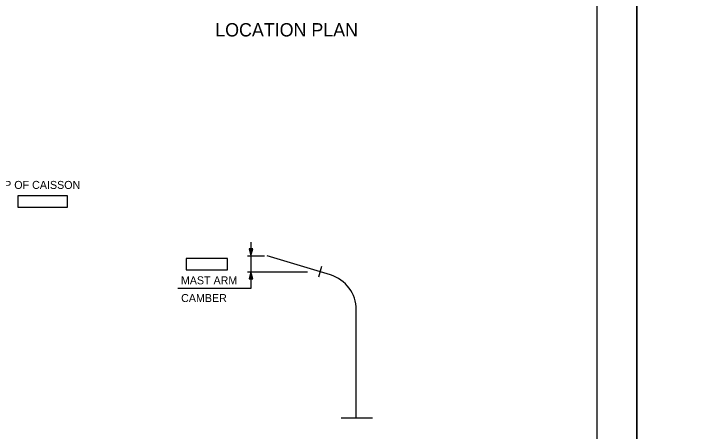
# Model space of a CAD drawing. Extents: x 640117 to 642655, y 297247 to 298435.
# Drawn here: x 640724.9 to 640985.6, y 297508.5 to 297665 of the extents above; entities that cross this region are included whole.
import ezdxf

# ---------------------------------------------------------------- set-up
doc = ezdxf.new("R2010")
doc.units = 0
for name, color, linetype in [('10', 7, 'Continuous'), ('2', 7, 'Continuous'), ('20', 7, 'Continuous'), ('50', 7, 'Continuous'), ('53', 7, 'Continuous'), ('PLT-BNDY', 7, 'Continuous')]:
    doc.layers.add(name, color=color, linetype=linetype)

msp = doc.modelspace()

# ---------------------------------------------------------------- linework, layer by layer
at = {"layer": '10'}
for p, q in [((640813.14, 297576.86), (640813.8, 297574.21)), ((640814.46, 297576.86), (640813.14, 297576.86)), ((640813.34, 297576.7), (640813.8, 297574.86)), ((640814.26, 297576.7), (640813.34, 297576.7)), ((640813.54, 297576.55), (640813.8, 297575.51)), ((640814.06, 297576.55), (640813.54, 297576.55)), ((640813.72, 297576.48), (640813.8, 297576.15)), ((640813.8, 297574.21), (640814.46, 297576.86)), ((640813.8, 297574.86), (640814.26, 297576.7)), ((640813.8, 297575.51), (640814.06, 297576.55)), ((640813.8, 297576.15), (640813.88, 297576.47)), ((640812.47, 297574.21), (640818.85, 297574.21)), ((640812.47, 297568.23), (640834.98, 297568.23)), ((640813.8, 297568.23), (640813.14, 297565.58)), ((640813.8, 297567.58), (640813.34, 297565.74)), ((640814.46, 297565.58), (640813.8, 297568.23)), ((640814.26, 297565.74), (640813.8, 297567.58)), ((640813.14, 297565.58), (640814.46, 297565.58)), ((640813.34, 297565.74), (640814.26, 297565.74)), ((640813.8, 297566.93), (640813.54, 297565.89)), ((640813.54, 297565.89), (640814.06, 297565.89)), ((640813.8, 297566.29), (640813.72, 297565.97)), ((640814.06, 297565.89), (640813.8, 297566.93)), ((640813.88, 297565.96), (640813.8, 297566.29)), ((640813.8, 297561.93), (640786.43, 297561.93))]:
    msp.add_line(p, q, dxfattribs=at)
msp.add_lwpolyline([(640813.8, 297579.34), (640813.8, 297561.93)], dxfattribs=at)
at = {"layer": '2'}
msp.add_line((640943.46, 297826.46), (640943.46, 297262.46), dxfattribs=at)
for points in [[(640726.36, 297592.43), (640745.07, 297592.43), (640745.07, 297596.68), (640726.36, 297596.68)], [(640789.56, 297568.94), (640805, 297568.94), (640805, 297573.19), (640789.56, 297573.19)]]:
    msp.add_lwpolyline(points, close=True, dxfattribs=at)
at = {"layer": '20'}
for p, q in [((640843.62, 297567.05), (640819.84, 297574.21)), ((640840.3, 297570.19), (640839.12, 297566.26)), ((640853.3, 297513.47), (640853.3, 297554.02)), ((640847.62, 297513.47), (640859.38, 297513.47))]:
    msp.add_line(p, q, dxfattribs=at)
at = {"layer": '50'}
msp.add_arc((640839.69, 297554.02), 13.6, 0, 73.2303, dxfattribs=at)
at = {"layer": 'PLT-BNDY'}
for points in [[(640117.46, 297841.46), (640958.46, 297841.46), (640958.46, 297247.46), (640117.46, 297247.46)], [(640958.46, 297841.46), (641799.46, 297841.46), (641799.46, 297247.46), (640958.46, 297247.46)]]:
    msp.add_lwpolyline(points, close=True, dxfattribs=at)

# ---------------------------------------------------------------- texts
at = {"layer": '10'}
for s, p in [('MAST ARM', (640787.56, 297563.51)), ('CAMBER', (640787.64, 297556.88))]:
    msp.add_text(s, height=2.992, dxfattribs=at).set_placement(p)
at = {"layer": '2'}
msp.add_text('LOCATION PLAN', height=5, dxfattribs=at).set_placement((640800.43, 297656.49))
at = {"layer": '53'}
msp.add_text('TOP OF CAISSON', height=3, dxfattribs=at).set_placement((640715.72, 297599.31))

doc.saveas('drawing.dxf')
